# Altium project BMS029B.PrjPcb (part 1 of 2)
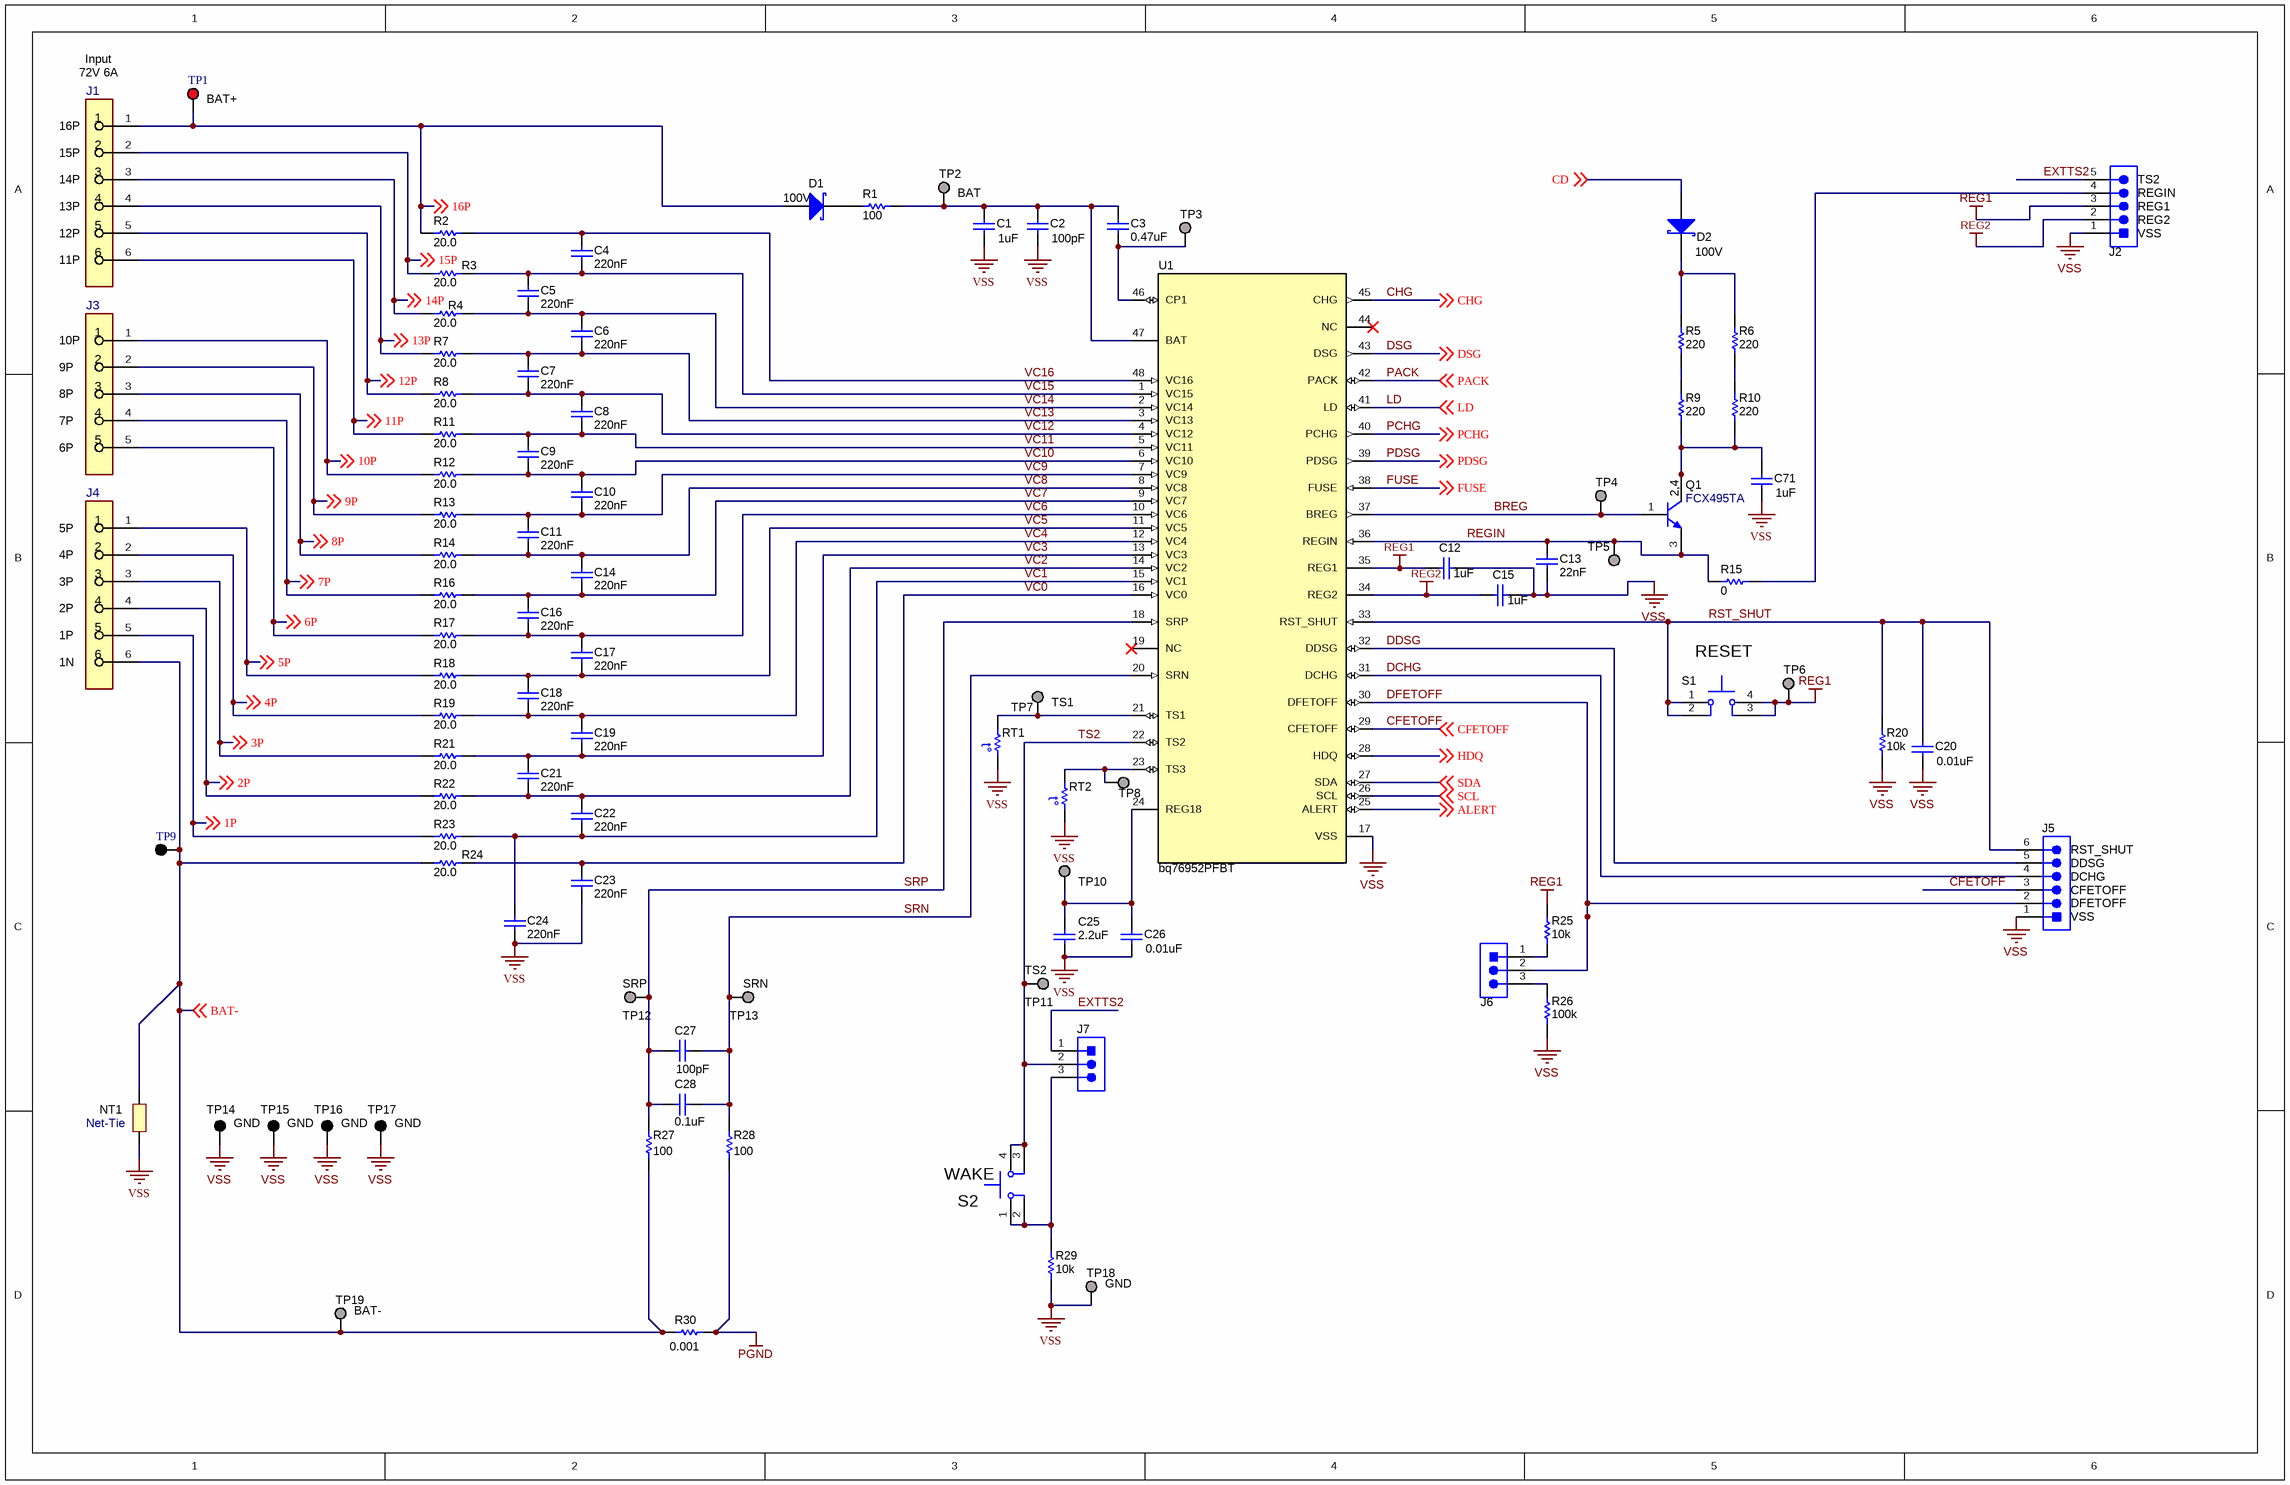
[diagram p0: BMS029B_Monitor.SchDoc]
PCB_Rev: B; PRJ_Customer: Public Release; PRJ_Number: BMS029; PRJ_Title: BQ76952EVM; SCH_Rev: B; TID: N/A
5 sheets, 371 parts. Net scope: global (net labels, ports and power ports of the same name join across sheets).
Board file: BMS029B.PcbDoc
Sheets:
  BMS029B_Monitor.SchDoc
  BMS029B_PinConfig.SchDoc
  BMS029B_FETs.SchDoc
  BMS029B_Interface.SchDoc
  BMS029B_Hardware.SchDoc

## Sheet BMS029B_Monitor.SchDoc: Monitor
size 431 x 279 mm; Date: Not shown in title block; ApprovedBy: Not shown in title block; CheckedBy: Not shown in title block; Author: Not shown in title block; CompanyName: Not shown in title block; Engineer: Not shown in title block; Organization: Not shown in title block; Address1: Not shown in title block; Address2: Not shown in title block; Address3: Not shown in title block; Address4: Not shown in title block; DocumentNumber: 1; Revision: Use project parameter SCH_Rev; SheetNumber: 1; SheetTotal: 5; PageSetup: Record=PageOptions¦CenterHorizontal=True¦CenterVertical=True¦PrintScale=1.00¦XCorrection=1.00¦YCorrection=1.00¦PrintKind=0¦BorderSize=5000000¦LeftOffset=0¦BottomOffset=0¦Orientation=2¦PaperLength=1000¦PaperWidth=1000¦Scale=100¦PaperSource=15¦PrintQuality=600¦MediaType=1¦DitherType=10¦PaperKind=Letter¦PrintScaleMode=1

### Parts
C1  ValueDisplayed: 1uF  [1206_180]  (hidden comment: C3216X7R2A105K160AA)
C2  ValueDisplayed: 100pF  [0603]  (hidden comment: GCM1885C2A101JA16D)
C3  ValueDisplayed: 0.47uF  [0805_HV]  (hidden comment: GCM219R71E474KA55D)
C4  Cap_F: 220nF  [0603S]  (hidden comment: C1608X7R1H224K080AB)
C5  Cap_F: 220nF  [0603S]  (hidden comment: C1608X7R1H224K080AB)
C6  Cap_F: 220nF  [0603S]  (hidden comment: C1608X7R1H224K080AB)
C7  Cap_F: 220nF  [0603S]  (hidden comment: C1608X7R1H224K080AB)
C8  Cap_F: 220nF  [0603S]  (hidden comment: C1608X7R1H224K080AB)
C9  Cap_F: 220nF  [0603S]  (hidden comment: C1608X7R1H224K080AB)
C10  Cap_F: 220nF  [0603S]  (hidden comment: C1608X7R1H224K080AB)
C11  Cap_F: 220nF  [0603S]  (hidden comment: C1608X7R1H224K080AB)
C12  ValueDisplayed: 1uF  [0805_HV]  (hidden comment: EMK212B7105KG-T)
C13  Cap_F: 22nF  [0603]  (hidden comment: C0603C223K4RACTU)
C14  Cap_F: 220nF  [0603S]  (hidden comment: C1608X7R1H224K080AB)
C15  ValueDisplayed: 1uF  [0805_HV]  (hidden comment: EMK212B7105KG-T)
C16  Cap_F: 220nF  [0603S]  (hidden comment: C1608X7R1H224K080AB)
C17  Cap_F: 220nF  [0603S]  (hidden comment: C1608X7R1H224K080AB)
C18  Cap_F: 220nF  [0603S]  (hidden comment: C1608X7R1H224K080AB)
C19  Cap_F: 220nF  [0603S]  (hidden comment: C1608X7R1H224K080AB)
C20  ValueDisplayed: 0.01uF  [0603]  (hidden comment: 885012206040)
C21  Cap_F: 220nF  [0603S]  (hidden comment: C1608X7R1H224K080AB)
C22  Cap_F: 220nF  [0603S]  (hidden comment: C1608X7R1H224K080AB)
C23  Cap_F: 220nF  [0603S]  (hidden comment: C1608X7R1H224K080AB)
C24  Cap_F: 220nF  [0603S]  (hidden comment: C1608X7R1H224K080AB)
C25  ValueDisplayed: 2.2uF  [0805_HV]  (hidden comment: EMK212B7225KG-T)
C26  ValueDisplayed: 0.01uF  [0603]  (hidden comment: 885012206040)
C27  ValueDisplayed: 100pF  [0603]  (hidden comment: C0603C101J5GACTU)
C28  ValueDisplayed: 0.1uF  [0603]  (hidden comment: 885012206095)
C71  ValueDisplayed: 1uF  [1206_180]  (hidden comment: C3216X7R2A105K160AA)
D1  value 100V  [SOD-123]  (hidden comment: BAT46W-7-F)
D2  value 100V  [SOD-123]  (hidden comment: BAT46W-7-F)
J1  OSTTE060161  [FP-OSTTE060161_HDR6-MFG]  (value not drawn)
J2  PEC05SAAN  [Sullins_PxC05SAAN]  (value not drawn)
J3  OSTTE050161  [FP-OSTTE050161_HDR5-MFG]  (value not drawn)
J4  OSTTE060161  [FP-OSTTE060161_HDR6-MFG]  (value not drawn)
J5  PEC06SAAN  [Sullins_PEC06SAAN]  (value not drawn)
J6  87898-0304  [Molex_87898-0304]  (value not drawn)
J7  87898-0304  [Molex_87898-0304]  (value not drawn)
NT1  Net-Tie  [Net-Tie_10milWide_30milLong]  (net tie, no BOM)
Q1  FCX495TA  [SOT-89-3]
R1  ValueDisplayed: 100  [0603]  (hidden comment: Resistor)
R2  ValueDisplayed: 20.0  [1206]  (hidden comment: CRCW120620R0FKEA)
R3  ValueDisplayed: 20.0  [1206]  (hidden comment: CRCW120620R0FKEA)
R4  ValueDisplayed: 20.0  [1206]  (hidden comment: CRCW120620R0FKEA)
R5  ValueDisplayed: 220  [2512]  (hidden comment: CRCW2512220RJNEG)
R6  ValueDisplayed: 220  [2512]  (hidden comment: CRCW2512220RJNEG)
R7  ValueDisplayed: 20.0  [1206]  (hidden comment: CRCW120620R0FKEA)
R8  ValueDisplayed: 20.0  [1206]  (hidden comment: CRCW120620R0FKEA)
R9  ValueDisplayed: 220  [2512]  (hidden comment: CRCW2512220RJNEG)
R10  ValueDisplayed: 220  [2512]  (hidden comment: CRCW2512220RJNEG)
R11  ValueDisplayed: 20.0  [1206]  (hidden comment: CRCW120620R0FKEA)
R12  ValueDisplayed: 20.0  [1206]  (hidden comment: CRCW120620R0FKEA)
R13  ValueDisplayed: 20.0  [1206]  (hidden comment: CRCW120620R0FKEA)
R14  ValueDisplayed: 20.0  [1206]  (hidden comment: CRCW120620R0FKEA)
R15  ValueDisplayed: 0  [0603]  (hidden comment: CRCW06030000Z0EA)
R16  ValueDisplayed: 20.0  [1206]  (hidden comment: CRCW120620R0FKEA)
R17  ValueDisplayed: 20.0  [1206]  (hidden comment: CRCW120620R0FKEA)
R18  ValueDisplayed: 20.0  [1206]  (hidden comment: CRCW120620R0FKEA)
R19  ValueDisplayed: 20.0  [1206]  (hidden comment: CRCW120620R0FKEA)
R20  ValueDisplayed: 10k  [0603]  (hidden comment: CRCW060310K0JNEA)
R21  ValueDisplayed: 20.0  [1206]  (hidden comment: CRCW120620R0FKEA)
R22  ValueDisplayed: 20.0  [1206]  (hidden comment: CRCW120620R0FKEA)
R23  ValueDisplayed: 20.0  [1206]  (hidden comment: CRCW120620R0FKEA)
R24  ValueDisplayed: 20.0  [1206]  (hidden comment: CRCW120620R0FKEA)
R25  ValueDisplayed: 10k  [0603]  (hidden comment: CRCW060310K0JNEA)
R26  ValueDisplayed: 100k  [0603]  (hidden comment: CRCW0603100KJNEA)
R27  ValueDisplayed: 100  [0603]  (hidden comment: Resistor)
R28  ValueDisplayed: 100  [0603]  (hidden comment: Resistor)
R29  ValueDisplayed: 10k  [0603]  (hidden comment: CRCW060310K0JNEA)
R30  ValueDisplayed: 0.001  [1210M]  (hidden comment: Resistor)
RT1  Thermistor  [THERMISTOR_103AT-2]  (value not drawn)
RT2  Thermistor  [THERMISTOR_103AT-2]  (value not drawn)
S1  SW_KST221JLFS  [SW_KST221JLFS]  (value not drawn)
S2  SW_KST221JLFS  [SW_KST221JLFS]  (value not drawn)
TP1  TESTPOINT  [Keystone5010]  (value not drawn)
TP2  TESTPOINT  [TP_VIA_060RND040]  (value not drawn)  (no BOM)
TP3  TESTPOINT  [TP_VIA_060RND040]  (value not drawn)  (no BOM)
TP4  TESTPOINT  [TP_VIA_060RND040]  (value not drawn)  (no BOM)
TP5  TESTPOINT  [TP_VIA_060RND040]  (value not drawn)  (no BOM)
TP6  TESTPOINT  [TP_VIA_060RND040]  (value not drawn)  (no BOM)
TP7  TESTPOINT  [TP_VIA_060RND040]  (value not drawn)  (no BOM)
TP8  TESTPOINT  [TP_VIA_060RND040]  (value not drawn)  (no BOM)
TP9  TESTPOINT  [Keystone5011]  (value not drawn)
TP10  TESTPOINT  [TP_50MIL-25MILHOLE]  (value not drawn)  (no BOM)
TP11  TESTPOINT  [TP_50MIL-25MILHOLE]  (value not drawn)  (no BOM)
TP12  TESTPOINT  [TP_50MIL-25MILHOLE]  (value not drawn)  (no BOM)
TP13  TESTPOINT  [TP_50MIL-25MILHOLE]  (value not drawn)  (no BOM)
TP14  5006  [Keystone5006]  (value not drawn)
TP15  5006  [Keystone5006]  (value not drawn)
TP16  5006  [Keystone5006]  (value not drawn)
TP17  5006  [Keystone5006]  (value not drawn)
TP18  TESTPOINT  [TP_VIA_060RND040]  (value not drawn)  (no BOM)
TP19  TESTPOINT  [TP_VIA_060RND040]  (value not drawn)  (no BOM)
U1  bq76952PFBT  [PFB0048A_N]

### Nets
PGND: R28.1 R30.1
REG1: C12.2 J2.3 R25.1 S1.3 S1.4 TP6.1 U1.35(REG1)
REG2: C15.2 J2.2 U1.34(REG2)
VSS: C1.2 C2.2 C12.1 C13.1 C15.1 C20.2 C23.2 C24.2 C25.1 C26.2 C71.2 J2.1 J5.1 NT1.1 R20.2 R26.1 R29.1 RT1.2 RT2.2 TP14.1 TP15.1 TP16.1 TP17.1 TP18.1 U1.17(VSS)
1P: J4.5 R23.1 ; off-sheet 1P
2P: J4.4 R22.1 ; off-sheet 2P
3P: J4.3 R21.1 ; off-sheet 3P
4P: J4.2 R19.1 ; off-sheet 4P
5P: J4.1 R18.1 ; off-sheet 5P
6P: J3.5 R17.1 ; off-sheet 6P
7P: J3.4 R16.1 ; off-sheet 7P
8P: J3.3 R14.1 ; off-sheet 8P
9P: J3.2 R13.1 ; off-sheet 9P
10P: J3.1 R12.1 ; off-sheet 10P
11P: J1.6 R11.1 ; off-sheet 11P
12P: J1.5 R8.1 ; off-sheet 12P
13P: J1.4 R7.1 ; off-sheet 13P
14P: J1.3 R4.1 ; off-sheet 14P
15P: J1.2 R3.1 ; off-sheet 15P
16P: D1.2(A) J1.1 R2.1 TP1.1 ; off-sheet 16P
ALERT: U1.25(ALERT) ; off-sheet ALERT
BAT-: J4.6 NT1.2 R24.1 R27.1 R30.2 TP9.1 TP19.1 ; off-sheet BAT-
BREG: Q1.1(B) TP4.1 U1.37(BREG)
CD: D2.2(A) ; off-sheet CD
CFETOFF: J5.3 U1.29(CFETOFF) ; off-sheet CFETOFF
CHG: U1.45(CHG) ; off-sheet CHG
DCHG: J5.4 U1.31(DCHG)
DDSG: J5.5 U1.32(DDSG)
DFETOFF: J5.2 J6.2 U1.30(DFETOFF)
DSG: U1.43(DSG) ; off-sheet DSG
EXTTS2: J2.5 J7.1
FUSE: U1.38(FUSE) ; off-sheet FUSE
HDQ: U1.28(HDQ) ; off-sheet HDQ
LD: U1.41(LD) ; off-sheet LD
PACK: U1.42(PACK) ; off-sheet PACK
PCHG: U1.40(PCHG) ; off-sheet PCHG
PDSG: U1.39(PDSG) ; off-sheet PDSG
REGIN: C13.2 Q1.3(E) R15.1 TP5.1 U1.36(REGIN)
RST_SHUT: C20.1 J5.6 R20.1 S1.1 S1.2 U1.33(RST_SHUT)
SCL: U1.26(SCL) ; off-sheet SCL
SDA: U1.27(SDA) ; off-sheet SDA
SRN: C27.1 C28.2 R28.2 TP13.1 U1.20(SRN)
SRP: C27.2 C28.1 R27.2 TP12.1 U1.18(SRP)
TS2: J7.2 S2.3 S2.4 TP11.1 U1.22(TS2)
VC0: C23.1 R24.2 U1.16(VC0)
VC1: C22.2 C24.1 R23.2 U1.15(VC1)
VC2: C21.2 C22.1 R22.2 U1.14(VC2)
VC3: C19.2 C21.1 R21.2 U1.13(VC3)
VC4: C18.2 C19.1 R19.2 U1.12(VC4)
VC5: C17.2 C18.1 R18.2 U1.11(VC5)
VC6: C16.2 C17.1 R17.2 U1.10(VC6)
VC7: C14.2 C16.1 R16.2 U1.9(VC7)
VC8: C11.2 C14.1 R14.2 U1.8(VC8)
VC9: C10.2 C11.1 R13.2 U1.7(VC9)
VC10: C9.2 C10.1 R12.2 U1.6(VC10)
VC11: C8.2 C9.1 R11.2 U1.5(VC11)
VC12: C7.2 C8.1 R8.2 U1.4(VC12)
VC13: C6.2 C7.1 R7.2 U1.3(VC13)
VC14: C5.2 C6.1 R4.2 U1.2(VC14)
VC15: C4.2 C5.1 R3.2 U1.1(VC15)
VC16: C4.1 R2.2 U1.48(VC16)
NetC1_1: C1.1 C2.1 C3.1 R1.1 TP2.1 U1.47(BAT)
NetC3_2: C3.2 TP3.1 U1.46(CP1)
NetC25_2: C25.2 C26.1 TP10.1 U1.24(REG18)
NetC71_1: C71.1 Q1.2(C) Q1.4(C) R9.1 R10.1
NetD1_1: D1.1(K) R1.2
NetD2_1: D2.1(K) R5.2 R6.2
NetJ2_4: J2.4 R15.2
NetJ6_1: J6.1 R25.2
NetJ6_3: J6.3 R26.2
NetJ7_3: J7.3 R29.2 S2.1 S2.2
NetR5_1: R5.1 R9.2
NetR6_1: R6.1 R10.2
NetRT1_1: RT1.1 TP7.1 U1.21(TS1)
NetRT2_1: RT2.1 TP8.1 U1.23(TS3)

Not connected (* = marked no-connect by the designer): U1 19(NC)* 44(NC)*

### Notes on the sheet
- Input
- (near J1) 72V 6A
- (near TP1) BAT+
- (near J1) 15P
- (near J1) 16P
- (near J1) 13P
- (near J1) 12P
- (near J1) 14P
- BAT
- (near J2) TS2
- (near J2) REGIN
- (near J2) REG1
- (near J2) VSS
- (near J2) REG2
- (near J1) 11P
- (near J3) 9P
- (near J3) 10P
- (near J3) 7P
- (near J3) 8P
- (near J3) 6P
- (near J4) 4P
- (near J4) 5P
- (near J4) 2P
- (near J4) 1P
- (near J4) 3P
- (near J4) 1N
- (near TP7) TS1
- RESET
- (near J5) DFETOFF
- (near J5) DDSG
- (near J5) DCHG
- (near J5) RST_SHUT
- (near J5) CFETOFF
- (near TP11) TS2
- (near J5) VSS
- (near TP12) SRP
- (near TP13) SRN
- GND
- (near TP17) GND
- (near S2) WAKE
- (near TP18) GND
- (near TP19) BAT-

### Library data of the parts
C1 C71 = CMP-0008710-2: CAP, CERM, 1 uF, 100 V, +/- 10%, X7R, 1206; Manufacturer: TDK; TaMin_C: -55°C; ESR_ohm: 4.575m; Polarized: N; SizeAreaWB_mm2: 10.92; Value1: 0.004575 ohm; U/M: EA; Value: 1uF; TaMax_C: 125°C; SizeZ_mm: 1.8; SizeX_mm: 3.2; SizeY_mm: 1.6; Value2: 100V; SizeArea_mm2: 5.12; Cap_F: 1µF; IRMS_A: 3.39639A; AEC Category: Q200
C2 = CMP-0007130-4: CAP, CERM, 100 pF, 100 V, +/- 5%, C0G/NP0, AEC-Q200 Grade 1, 0603; Manufacturer: MuRata; TaMin_C: -55°C; Polarized: N; SizeAreaWB_mm2: 4.68; Value1: Unknown; U/M: EA; TaMax_C: 125°C; SizeZ_mm: 1; SizeX_mm: 1.6; SizeY_mm: 0.8; Value2: 100V; SizeArea_mm2: 1.28; AEC Qualified: Y; AEC Category: Q200; Value: 100pF
C3 = CMP-0008010-2: CAP, CERM, 0.47 uF, 25 V, +/- 10%, X7R, AEC-Q200 Grade 1, 0805; Manufacturer: MuRata; TaMin_C: -55°C; Polarized: N; SizeAreaWB_mm2: 6.75; Value1: Unknown; U/M: EA; Value: 0.47uF; TaMax_C: 125°C; SizeZ_mm: 1.45; SizeX_mm: 2; SizeY_mm: 1.25; Cap_Case: 0805; Value2: 25V; SizeArea_mm2: 2.5; AEC Qualified: Y; Cap_F: 470nF; AEC Grade: 1; AEC Category: Q200
C4-C11 C14 C16-C19 C21-C24 = CMP-0007047-4: CAP, CERM, 0.22 uF, 50 V, +/- 10%, X7R, 0603; Manufacturer: TDK; TaMin_C: -55°C; ESR_ohm: 0.021699; Polarized: N; SizeAreaWB_mm2: 4.68; Value1: 0.021699 ohm; U/M: EA; Value: 0.22uF; TaMax_C: 125°C; SizeZ_mm: 1; SizeX_mm: 1.6; SizeY_mm: 0.8; Cap_Case: 0603; Value2: 50V; SizeArea_mm2: 1.28; IRMS_A: 1.12496A; AEC Category: Q200
C12 C15 = CMP-0008000-2: CAP, CERM, 1 uF, 16 V, +/- 10%, X7R, 0805; Manufacturer: Taiyo Yuden; TaMin_C: -55°C; Polarized: N; SizeAreaWB_mm2: 6.75; Value1: Unknown; U/M: EA; Value: 1uF; TaMax_C: 125°C; SizeZ_mm: 1.45; SizeX_mm: 2; SizeY_mm: 1.25; Cap_Case: 0805; Value2: 16V; SizeArea_mm2: 2.5; Cap_F: 1µF; AEC Category: Q200
C13 = CMP-0006900-4: CAP, CERM, 0.022 uF, 16 V, +/- 10%, X7R, 0603; Manufacturer: Kemet; TaMin_C: -55°C; Polarized: N; SizeAreaWB_mm2: 4.68; Value1: Unknown; U/M: EA; TaMax_C: 125°C; SizeZ_mm: 1; SizeX_mm: 1.6; SizeY_mm: 0.8; Value2: 16V; SizeArea_mm2: 1.28; AEC Category: Q200
C20 C26 = CMP-0006828-4: CAP, CERM, 0.01 uF, 16 V, +/- 10%, X7R, 0603; Manufacturer: Wurth Elektronik; TaMin_C: -55°C; Polarized: N; SizeAreaWB_mm2: 4.68; Value1: Unknown; U/M: EA; Value: 0.01uF; TaMax_C: 125°C; SizeZ_mm: 1; SizeX_mm: 1.6; SizeY_mm: 0.8; Value2: 16V; SizeArea_mm2: 1.28; Cap_F: 10nF; AEC Category: Q200
C25 = CMP-0008001-2: CAP, CERM, 2.2 uF, 16 V, +/- 10%, X7R, 0805; Manufacturer: Taiyo Yuden; TaMin_C: -55°C; Polarized: N; SizeAreaWB_mm2: 6.75; Value1: Unknown; U/M: EA; Value: 2.2uF; TaMax_C: 125°C; SizeZ_mm: 1.45; SizeX_mm: 2; SizeY_mm: 1.25; Cap_Case: 0805; Value2: 16V; SizeArea_mm2: 2.5; Cap_F: 2.2µF; AEC Category: Q200
C27 = CMP-0006841-4: CAP, CERM, 100 pF, 50 V, +/- 5%, C0G/NP0, 0603; Manufacturer: Kemet; TaMin_C: -55°C; Polarized: N; SizeAreaWB_mm2: 4.68; Value1: Unknown; U/M: EA; Value: 100pF; TaMax_C: 125°C; SizeZ_mm: 1; SizeX_mm: 1.6; SizeY_mm: 0.8; Value2: 50V; SizeArea_mm2: 1.28; AEC Category: Q200
C28 = CMP-0006837-4: CAP, CERM, 0.1 uF, 50 V, +/- 10%, X7R, 0603; Manufacturer: Wurth Elektronik; TaMin_C: -55°C; Polarized: N; SizeAreaWB_mm2: 4.68; Value1: Unknown; U/M: EA; Value: 0.1uF; TaMax_C: 125°C; SizeZ_mm: 1; SizeX_mm: 1.6; SizeY_mm: 0.8; Value2: 50V; SizeArea_mm2: 1.28; Cap_F: 100nF; AEC Category: Q200
D1 D2 = CMP-0028450-2: Diode, Schottky, 100 V, 0.15 A, SOD-123; Manufacturer: Diodes Inc.; Io_A: 150mA; SizeArea_mm2: 6.545; SizeX_mm: 3.85; Value2: 0.6V; Value1: 0.15A; AEC Category: Q101; SizeZ_mm: 1.35; SizeY_mm: 1.7; Green_Lifecycle: Active; Green_REACh: Passed; SizeAreaWB_mm2: 13.095; Vf_V: 600mV
J1 J4 = CMP-0087050-1: TERM BLOCK 3.5MM VERT 6POS PCB; Manufacturer: On Shore Technology; ContactFinish: Tin; Current_A: 10A; Voltage_V: 300V; Row_Count: 1
J2 = CMP-0054597-1: Header, 2.54mm, 5x1, Tin, TH; Manufacturer: Sullins Connector Solutions; CNHeader: TRUE; Current_A: 3A; Green_Lifecycle: Not Set; Shrouded: N; Gender: Male; Green_REACh: Incomplete; Voltage_V: 1.8kV; Row_Count: 1; Pitch_mm: 2.54; CT: FALSE; Cert_UL: Y
J3 = CMP-0087049-1: TERM BLOCK 3.5MM VERT 5POS PCB; Manufacturer: On Shore Technology; Row_Count: 1; ContactFinish: Tin; Current_A: 10A; Voltage_V: 300V
J5 = CMP-0054567-1: Header, 100mil, 6x1, Tin, TH; Manufacturer: Sullins Connector Solutions; CNHeader: TRUE; Green_Lifecycle: Not Set; Green_REACh: Incomplete; CT: FALSE
J6 J7 = CMP-0075388-1: Header, 2.54mm, 3x1, Gold, SMT; Manufacturer: Molex; Pitch_mm: 2.54; Gender: Male; Cert_CSA: Y; Current_A: 3A; Voltage_V: 250V; CT: False; Shrouded: N; Row_Count: 1; CNHeader: True
NT1 = CMP-0078142-3: Single point connection between nets.
Q1 = CMP-0000510-2: Transistor, NPN, 150 V, 1 A, AEC-Q101, SOT-89; Manufacturer: Diodes Inc.; TaMax_C: 150°C; Value2: 300; Value1: 1 A; Vcesat1_V: 200mV; SizeX_mm: 4.1; SizeY_mm: 4.5; TaMin_C: -65°C; IcRated_A: 1A; CompType: BJT; SizeZ_mm: 1.5; AEC Qualified: Y; Value: 150 V; SizeArea_mm2: 18.45; NPN: 1; Vceo_V: 150V; PNP: 0; AEC Category: Q101; SizeAreaWB_mm2: 28.05; U/M: EA
R1 R27 R28 = CMP-0025700-4: RES, 100, 5%, 0.1 W, AEC-Q200 Grade 0, 0603; PartNumber: CRCW0603100RJNEA; Manufacturer: Vishay-Dale; Value: 100; Value_Code: 100R; Power_W: 100mW; Value2: 0.1W; VDC_V: 75V; TempCo: 200 ppm/C; EIA_Code: E24; U/M: EA; SizeArea_mm2: 1.28; SizeX_mm: 1.6; SizeY_mm: 0.8; SizeZ_mm: 1; AEC Category: Q200; AEC Qualified: Y; AEC Grade: 0
R2 R14 = CMP-0016781-3: RES, 20.0, 1%, 0.25 W, AEC-Q200 Grade 0, 1206; Manufacturer: Vishay-Dale; CompType: Resistor; Value: 20.0; Res_ohm: 20; Value_Code: 20R0; Power_W: 250mW; Value2: 0.25W; VDC_V: 200V; TempCo: 100 ppm/C; EIA_Code: E96; SizeArea_mm2: 5.12; SizeX_mm: 3.2; SizeY_mm: 1.6; SizeZ_mm: 1.35; AEC Category: Q200; AEC Qualified: Y; AEC Grade: 0
R3 R4 R7 R8 R11-R13 R16-R19 R21-R24 = CMP-0016781-3: RES, 20.0, 1%, 0.25 W, AEC-Q200 Grade 0, 1206; Manufacturer: Vishay-Dale; Value: 20.0; Res_ohm: 20; Value_Code: 20R0; Power_W: 250mW; Value2: 0.25W; VDC_V: 200V; TempCo: 100 ppm/C; EIA_Code: E96; SizeArea_mm2: 5.12; SizeX_mm: 3.2; SizeY_mm: 1.6; SizeZ_mm: 1.35; AEC Category: Q200; AEC Qualified: Y; AEC Grade: 0
R5 R6 R9 R10 = CMP-0015916-3: RES, 220, 5%, 1 W, AEC-Q200 Grade 0, 2512; Manufacturer: Vishay-Dale; Power_W: 1W; TempCo: 200 ppm/C; Value_Code: 220R; Value: 220; EIA_Code: E24; SizeX_mm: 6.3; SizeY_mm: 3.2; SizeZ_mm: 0.71; SizeArea_mm2: 20.16; AEC Qualified: Y; VDC_V: 500V; AEC Grade: 0; AEC Category: Q200
R15 = CMP-0025697-4: RES, 0, 5%, 0.1 W, AEC-Q200 Grade 0, 0603; Manufacturer: Vishay-Dale; Value: 0; Value_Code: 0000; Power_W: 100mW; Value2: 0.1W; VDC_V: 75V; TempCo: 200 ppm/C; EIA_Code: E24; SizeArea_mm2: 1.28; SizeX_mm: 1.6; SizeY_mm: 0.8; SizeZ_mm: 1; AEC Category: Q200; AEC Qualified: Y
R20 R25 = CMP-0025701-4: RES, 10 k, 5%, 0.1 W, AEC-Q200 Grade 0, 0603; Manufacturer: Vishay-Dale; Power_W: 100mW; TempCo: 200 ppm/C; Value_Code: 10k0; Value: 10k; EIA_Code: E24; SizeX_mm: 1.6; SizeY_mm: 0.8; SizeZ_mm: 1; Value2: 0.1W; SizeArea_mm2: 1.28; AEC Qualified: Y; VDC_V: 75V; AEC Category: Q200; AEC Grade: 0
R26 = CMP-0025698-4: RES, 100 k, 5%, 0.1 W, AEC-Q200 Grade 0, 0603; Manufacturer: Vishay-Dale; Power_W: 100mW; TempCo: 200 ppm/C; Value: 100k; EIA_Code: E24; SizeX_mm: 1.6; SizeY_mm: 0.8; SizeZ_mm: 1; Value2: 0.1W; SizeArea_mm2: 1.28; AEC Qualified: Y; VDC_V: 75V; AEC Category: Q200; AEC Grade: 0
R29 = CMP-0025701-4: RES, 10 k, 5%, 0.1 W, AEC-Q200 Grade 0, 0603; Manufacturer: Vishay-Dale; Power_W: 100mW; TempCo: 200 ppm/C; Value_Code: 10k0; Value: 10k; EIA_Code: E24; SizeX_mm: 1.6; SizeY_mm: 0.8; SizeZ_mm: 1; Value2: 0.1W; SizeArea_mm2: 1.28; AEC Qualified: Y; VDC_V: 75V; AEC Grade: 0; AEC Category: Q200
R30 = CMP-0015200-2: RES, 0.001, 1%, 1 W, 1210; PartNumber: PMR25HZPFV1L00; Manufacturer: Rohm; Value: 0.001; Res_ohm: 1m; Value_Code: 1L000; Power_W: 1W; TempCo: 100 ppm/C; EIA_Code: E96; U/M: EA; SizeArea_mm2: 8; SizeAreaWB_mm2: 14.7; SizeX_mm: 3.2; SizeY_mm: 2.5; SizeZ_mm: 1.35; AEC Category: Q200; Green_Lifecycle: Active; Green_REACh: Passed
RT1 RT2 = CMP-0002341-2: Thermistor NTC, 10.0k ohm, 1%, Disc, 5x8.4 mm; PartNumber: 103AT-2; Manufacturer: SEMITEC Corporation; Power_W: 10mW; TaMin_C: -50°C; TaMax_C: 110°C; U/M: EA; Value: 10k
S1 S2 = CMP-0002132-2: Switch, Tactile, SPST-NO, SMT; Manufacturer: C&K Components; SymbolCreator: a0799628; VDC_V: 32V; SwitchFunction: Off-Mom; PositionCount: 1; CurrentRating_mA: 50A; Green_Lifecycle: Active; Green_REACh: Passed
TP1 = CMP-0055147-1: Test Point, Multipurpose, Red, TH; Manufacturer: Keystone; CNHeader: FALSE; Green_Lifecycle: Active; Green_REACh: Passed; ContactFinish: Silver; CT: TRUE
TP2-TP8 TP10-TP13 TP18 TP19 = CMP-0078143-2: TEST POINT.  No entry in BOM.
TP9 = CMP-0055148-1: Test Point, Multipurpose, Black, TH; Manufacturer: Keystone; CNHeader: FALSE; Green_Lifecycle: Active; Green_REACh: Passed; ContactFinish: Silver; CT: TRUE
TP14-TP17 = CMP-0055143-1: Test Point, Compact, Black, TH; Manufacturer: Keystone; ContactFinish: Silver; Green_Lifecycle: Active; Green_REACh: Passed; CNHeader: FALSE; CT: TRUE
U1 = CMP-0084229-1: Multicell Battery Monitor and Protection Family, PFB0048A (TQFP-48); Alternate PartNumber: bq76952PFBR; Alternate Manufacturer: Texas Instruments; SizeAreaWB_mm2: 121; SizeZ_mm: 1.2; SizeX_mm: 9; SizeArea_mm2: 81; CompType: IC; AEC Qualified: N; AEC Category: Q200

## Sheet BMS029B_PinConfig.SchDoc: Pin Configuration
size 431 x 279 mm; Date: Not shown in title block; ApprovedBy: Not shown in title block; CheckedBy: Not shown in title block; Author: Not shown in title block; CompanyName: Not shown in title block; DrawnBy: M Sunna; Engineer: Not shown in title block; Organization: Not shown in title block; Address1: Not shown in title block; Address2: Not shown in title block; Address3: Not shown in title block; Address4: Not shown in title block; DocumentNumber: 2; Revision: Use project parameter SCH_Rev; SheetNumber: 2; SheetTotal: 5; PageSetup: Record=PageOptions¦CenterHorizontal=True¦CenterVertical=True¦PrintScale=1.00¦XCorrection=1.00¦YCorrection=1.00¦PrintKind=0¦BorderSize=5000000¦LeftOffset=0¦BottomOffset=0¦Orientation=2¦PaperLength=1000¦PaperWidth=1000¦Scale=100¦PaperSource=15¦PrintQuality=600¦MediaType=1¦DitherType=10¦PaperKind=Letter¦PrintScaleMode=1
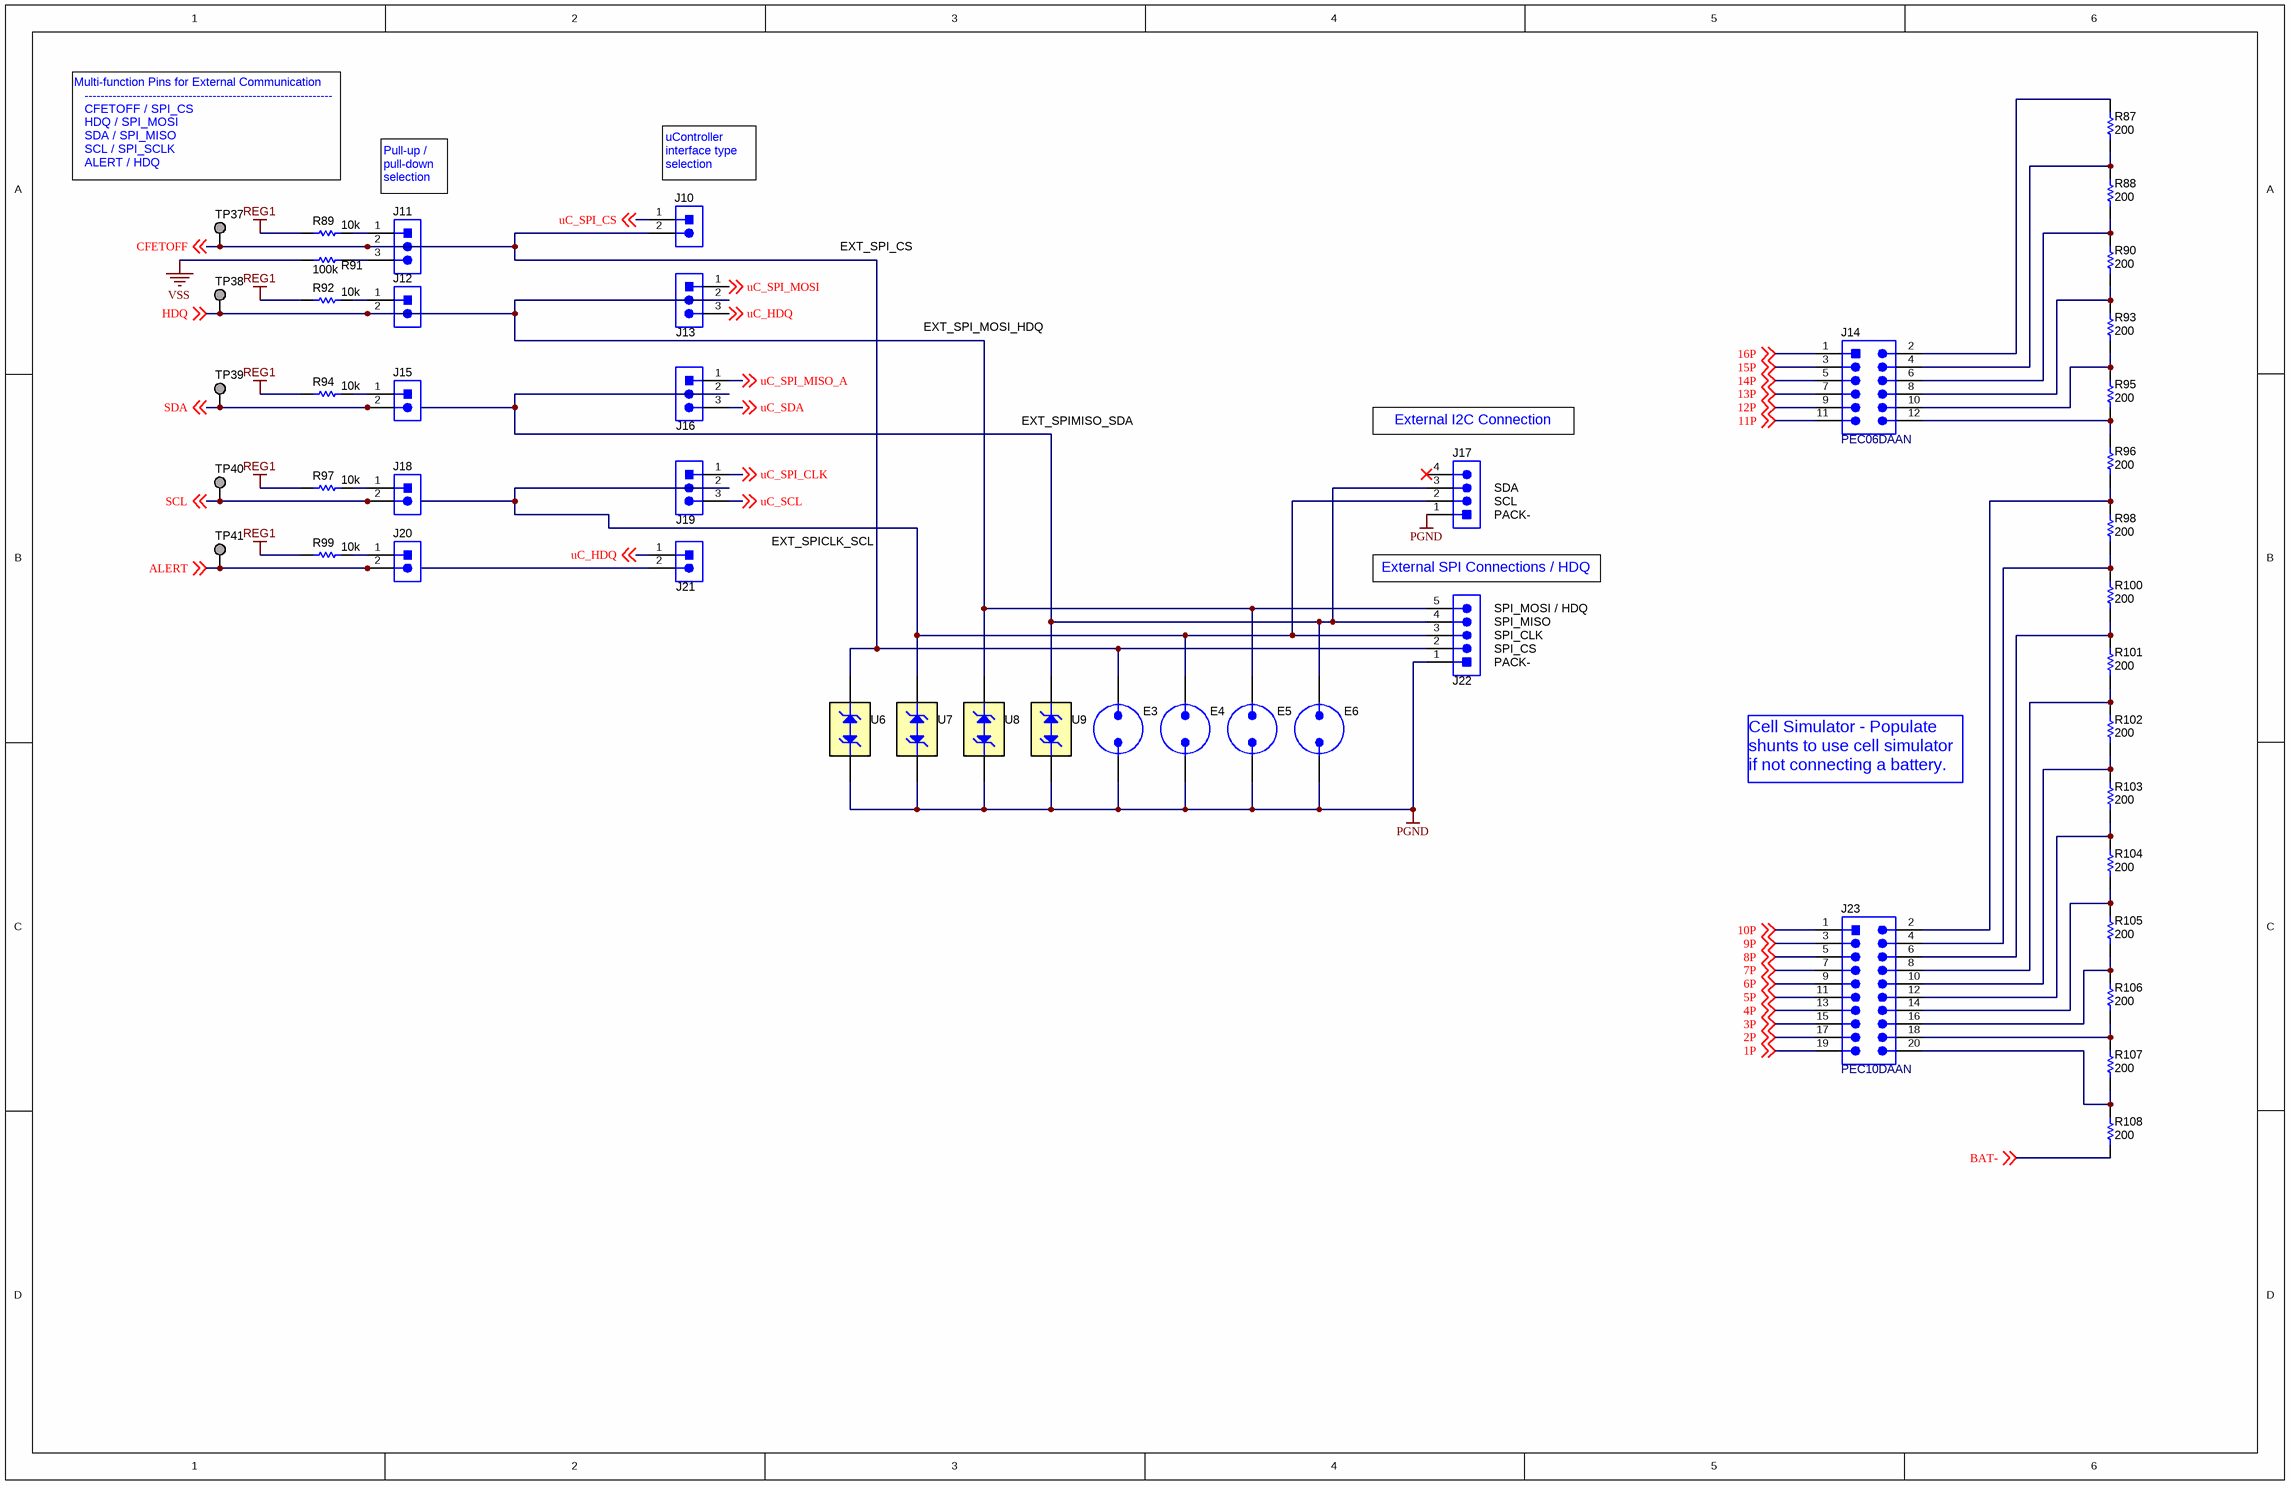
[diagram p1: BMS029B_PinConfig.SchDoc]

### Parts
E3  Spark Gap  [SPARK_GAP2]  (value not drawn)  (no BOM)
E4  Spark Gap  [SPARK_GAP2]  (value not drawn)  (no BOM)
E5  Spark Gap  [SPARK_GAP2]  (value not drawn)  (no BOM)
E6  Spark Gap  [SPARK_GAP2]  (value not drawn)  (no BOM)
J10  PEC02SAAN  [CONN_PEC02SAAN]  (value not drawn)
J11  87898-0304  [Molex_87898-0304]  (value not drawn)
J12  PEC02SAAN  [CONN_PEC02SAAN]  (value not drawn)
J13  87898-0304  [Molex_87898-0304]  (value not drawn)
J14  PEC06DAAN  [CONN_PEC06DAAN]
J15  PEC02SAAN  [CONN_PEC02SAAN]  (value not drawn)
J16  87898-0304  [Molex_87898-0304]  (value not drawn)
J17  22/05/3041  [CONN_22-05-3041]  (value not drawn)
J18  PEC02SAAN  [CONN_PEC02SAAN]  (value not drawn)
J19  87898-0304  [Molex_87898-0304]  (value not drawn)
J20  PEC02SAAN  [CONN_PEC02SAAN]  (value not drawn)
J21  PEC02SAAN  [CONN_PEC02SAAN]  (value not drawn)
J22  PEC05SAAN  [Sullins_PxC05SAAN]  (value not drawn)
J23  PEC10DAAN  [SULLINS_PEC10DAAN]
R87  ValueDisplayed: 200  [1206]  (hidden comment: CRCW1206200RFKEA)
R88  ValueDisplayed: 200  [1206]  (hidden comment: CRCW1206200RFKEA)
R89  ValueDisplayed: 10k  [0603]  (hidden comment: CRCW060310K0JNEA)
R90  ValueDisplayed: 200  [1206]  (hidden comment: CRCW1206200RFKEA)
R91  ValueDisplayed: 100k  [0603]  (hidden comment: CRCW0603100KJNEA)
R92  ValueDisplayed: 10k  [0603]  (hidden comment: CRCW060310K0JNEA)
R93  ValueDisplayed: 200  [1206]  (hidden comment: CRCW1206200RFKEA)
R94  ValueDisplayed: 10k  [0603]  (hidden comment: CRCW060310K0JNEA)
R95  ValueDisplayed: 200  [1206]  (hidden comment: CRCW1206200RFKEA)
R96  ValueDisplayed: 200  [1206]  (hidden comment: CRCW1206200RFKEA)
R97  ValueDisplayed: 10k  [0603]  (hidden comment: CRCW060310K0JNEA)
R98  ValueDisplayed: 200  [1206]  (hidden comment: CRCW1206200RFKEA)
R99  ValueDisplayed: 10k  [0603]  (hidden comment: CRCW060310K0JNEA)
R100  ValueDisplayed: 200  [1206]  (hidden comment: CRCW1206200RFKEA)
R101  ValueDisplayed: 200  [1206]  (hidden comment: CRCW1206200RFKEA)
R102  ValueDisplayed: 200  [1206]  (hidden comment: CRCW1206200RFKEA)
R103  ValueDisplayed: 200  [1206]  (hidden comment: CRCW1206200RFKEA)
R104  ValueDisplayed: 200  [1206]  (hidden comment: CRCW1206200RFKEA)
R105  ValueDisplayed: 200  [1206]  (hidden comment: CRCW1206200RFKEA)
R106  ValueDisplayed: 200  [1206]  (hidden comment: CRCW1206200RFKEA)
R107  ValueDisplayed: 200  [1206]  (hidden comment: CRCW1206200RFKEA)
R108  ValueDisplayed: 200  [1206]  (hidden comment: CRCW1206200RFKEA)
TP37  TESTPOINT  [TP_50MIL-25MILHOLE]  (value not drawn)  (no BOM)
TP38  TESTPOINT  [TP_50MIL-25MILHOLE]  (value not drawn)  (no BOM)
TP39  TESTPOINT  [TP_50MIL-25MILHOLE]  (value not drawn)  (no BOM)
TP40  TESTPOINT  [TP_50MIL-25MILHOLE]  (value not drawn)  (no BOM)
TP41  TESTPOINT  [TP_50MIL-25MILHOLE]  (value not drawn)  (no BOM)
U6  TPD1E10B06DPYR  [DPY0002A]  (value not drawn)
U7  TPD1E10B06DPYR  [DPY0002A]  (value not drawn)
U8  TPD1E10B06DPYR  [DPY0002A]  (value not drawn)
U9  TPD1E10B06DPYR  [DPY0002A]  (value not drawn)

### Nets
PGND: E3.2 E4.2 E5.2 E6.2 J17.1 J22.1 U6.2(A) U7.2(A) U8.2(A) U9.2(A)
REG1: R89.1 R92.1 R94.1 R97.1 R99.1
VSS: R91.1
1P: J23.19 ; off-sheet 1P
2P: J23.17 ; off-sheet 2P
3P: J23.15 ; off-sheet 3P
4P: J23.13 ; off-sheet 4P
5P: J23.11 ; off-sheet 5P
6P: J23.9 ; off-sheet 6P
7P: J23.7 ; off-sheet 7P
8P: J23.5 ; off-sheet 8P
9P: J23.3 ; off-sheet 9P
10P: J23.1 ; off-sheet 10P
11P: J14.11 ; off-sheet 11P
12P: J14.9 ; off-sheet 12P
13P: J14.7 ; off-sheet 13P
14P: J14.5 ; off-sheet 14P
15P: J14.3 ; off-sheet 15P
16P: J14.1 ; off-sheet 16P
ALERT: J20.2 J21.2 TP41.1 ; off-sheet ALERT
BAT-: R108.1 ; off-sheet BAT-
CFETOFF: E3.1 J10.2 J11.2 J22.2 TP37.1 U6.1(K) ; off-sheet CFETOFF
HDQ: E5.1 J12.2 J13.2 J22.5 TP38.1 U8.1(K) ; off-sheet HDQ
SCL: E4.1 J17.2 J18.2 J19.2 J22.3 TP40.1 U7.1(K) ; off-sheet SCL
SDA: E6.1 J15.2 J16.2 J17.3 J22.4 TP39.1 U9.1(K) ; off-sheet SDA
uC_HDQ: J13.3 J21.1 ; off-sheet uC_HDQ
uC_SCL: J19.3 ; off-sheet uC_SCL  [project net SCL2]
uC_SDA: J16.3 ; off-sheet uC_SDA  [project net SDA2]
uC_SPI_CLK: J19.1 ; off-sheet uC_SPI_CLK
uC_SPI_CS: J10.1 ; off-sheet uC_SPI_CS
uC_SPI_MISO_A: J16.1 ; off-sheet uC_SPI_MISO_A
uC_SPI_MOSI: J13.1 ; off-sheet uC_SPI_MOSI
NetJ11_1: J11.1 R89.2
NetJ11_3: J11.3 R91.2
NetJ12_1: J12.1 R92.2
NetJ14_2: J14.2 R87.2
NetJ14_4: J14.4 R87.1 R88.2
NetJ14_6: J14.6 R88.1 R90.2
NetJ14_8: J14.8 R90.1 R93.2
NetJ14_10: J14.10 R93.1 R95.2
NetJ14_12: J14.12 R95.1 R96.2
NetJ15_1: J15.1 R94.2
NetJ18_1: J18.1 R97.2
NetJ20_1: J20.1 R99.2
NetJ23_2: J23.2 R96.1 R98.2
NetJ23_4: J23.4 R98.1 R100.2
NetJ23_6: J23.6 R100.1 R101.2
NetJ23_8: J23.8 R101.1 R102.2
NetJ23_10: J23.10 R102.1 R103.2
NetJ23_12: J23.12 R103.1 R104.2
NetJ23_14: J23.14 R104.1 R105.2
NetJ23_16: J23.16 R105.1 R106.2
NetJ23_18: J23.18 R106.1 R107.2
NetJ23_20: J23.20 R107.1 R108.2

Not connected (* = marked no-connect by the designer): J17 4*

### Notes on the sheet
- Multi-function Pins for External Communication
  --------------------------------------------------------------
  CFETOFF / SPI_CS
  HDQ / SPI_MOSI
  SDA / SPI_MISO
  SCL / SPI_SCLK
  ALERT / HDQ
- Pull-up / pull-down selection
- (near J10) uController interface type selection
- EXT_SPI_CS
- EXT_SPI_MOSI_HDQ
- EXT_SPIMISO_SDA
- (near J17) External I2C Connection
- (near J17) SDA
- (near J17) SCL
- EXT_SPICLK_SCL
- (near J17) PACK-
- External SPI Connections / HDQ
- (near J22) SPI_MISO
- (near J22) SPI_MOSI / HDQ
- (near J22) SPI_CLK
- (near J22) SPI_CS
- (near J22) PACK-
- Cell Simulator - Populate shunts to use cell simulator if not connecting a battery.

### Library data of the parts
E3-E6 = CMP-0079939-1
J10 J12 J15 J18 J20 J21 = CMP-0002337-1: Header, 100mil, 2x1, Tin, TH; Manufacturer: Sullins Connector Solutions; CNHeader: TRUE; Current_A: 3A; Green_Lifecycle: Not Set; Shrouded: N; Gender: Male; Green_REACh: Incomplete; Voltage_V: 1.8kV; Row_Count: 1; Pitch_mm: 2.54; CT: FALSE; Cert_UL: Y
J11 J13 J16 J19 = CMP-0075388-1: as J6 on sheet BMS029B_Monitor
J14 = CMP-0054551-2: Header, 100mil, 6x2, Tin, TH; Manufacturer: Sullins Connector Solutions; Current_A: 3A; Green_Lifecycle: Not Set; Shrouded: N; Gender: Male; Green_REACh: Incomplete; Voltage_V: 1.8kV; Row_Count: 2; RowSpacing_mm: 2.54; Cert_UL: Y
J17 = CMP-0055187-1: Header (friction lock), 100mil, 4x1, R/A, TH; Manufacturer: Molex; Green_Lifecycle: Active; Green_REACh: Passed; CNHeader: FALSE
J22 = CMP-0054597-1: as J2 on sheet BMS029B_Monitor
J23 = CMP-0054623-2: Header, 2.54mm, 10x2, Tin, TH; Manufacturer: Sullins Connector Solutions; Current_A: 3A; Green_Lifecycle: Not Set; Shrouded: N; Gender: Male; Green_REACh: Incomplete; Row_Count: 2; RowSpacing_mm: 2.54; Cert_UL: Y
R87 R88 R90 R93 R95 R96 R98 R100-R108 = CMP-0016776-3: RES, 200, 1%, 0.25 W, AEC-Q200 Grade 0, 1206; Manufacturer: Vishay-Dale; Power_W: 250mW; TempCo: 100 ppm/C; Value_Code: 200R; Value: 200; EIA_Code: E96; SizeX_mm: 3.2; SizeY_mm: 1.6; SizeZ_mm: 1.35; Value2: 0.25W; SizeArea_mm2: 5.12; AEC Qualified: Y; VDC_V: 200V; AEC Category: Q200; AEC Grade: 0
R89 R92 R94 R97 R99 = CMP-0025701-4: RES, 10 k, 5%, 0.1 W, AEC-Q200 Grade 0, 0603; Manufacturer: Vishay-Dale; Power_W: 100mW; TempCo: 200 ppm/C; Value_Code: 10k0; Value: 10k; EIA_Code: E24; SizeX_mm: 1.6; SizeY_mm: 0.8; SizeZ_mm: 1; Value2: 0.1W; SizeArea_mm2: 1.28; CompType: Resistor; AEC Qualified: Y; VDC_V: 75V; AEC Category: Q200; AEC Grade: 0
R91 = CMP-0025698-4: as R26 on sheet BMS029B_Monitor
TP37-TP41 = CMP-0078143-2: TEST POINT.  No entry in BOM.
U6-U9 = CMP-0043093-3: Single-Channel ESD in 0402 Package With 10pF Capacitance and 6V Breakdown, DPY0002A (X1SON-2); Manufacturer: Texas Instruments; Alternate PartNumber: TPD1E10B06DPYT; IEC 61000-4-2 Air-Gap(+/- kV): 30; Eco-Plan: TBD; IO Capacitance(Typ)(pF): 10; Breakdown Voltage(Min)(V): 6; AEC Category: Q200; AEC Qualified: N; CompType: IC; Green_Lifecycle: Active; Green_REACh: Passed; SizeAreaWB_mm2: 3.2; SizeArea_mm2: 0.6; SizeX_mm: 1.0; SizeZ_mm: 0.45; Rating: Catalog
